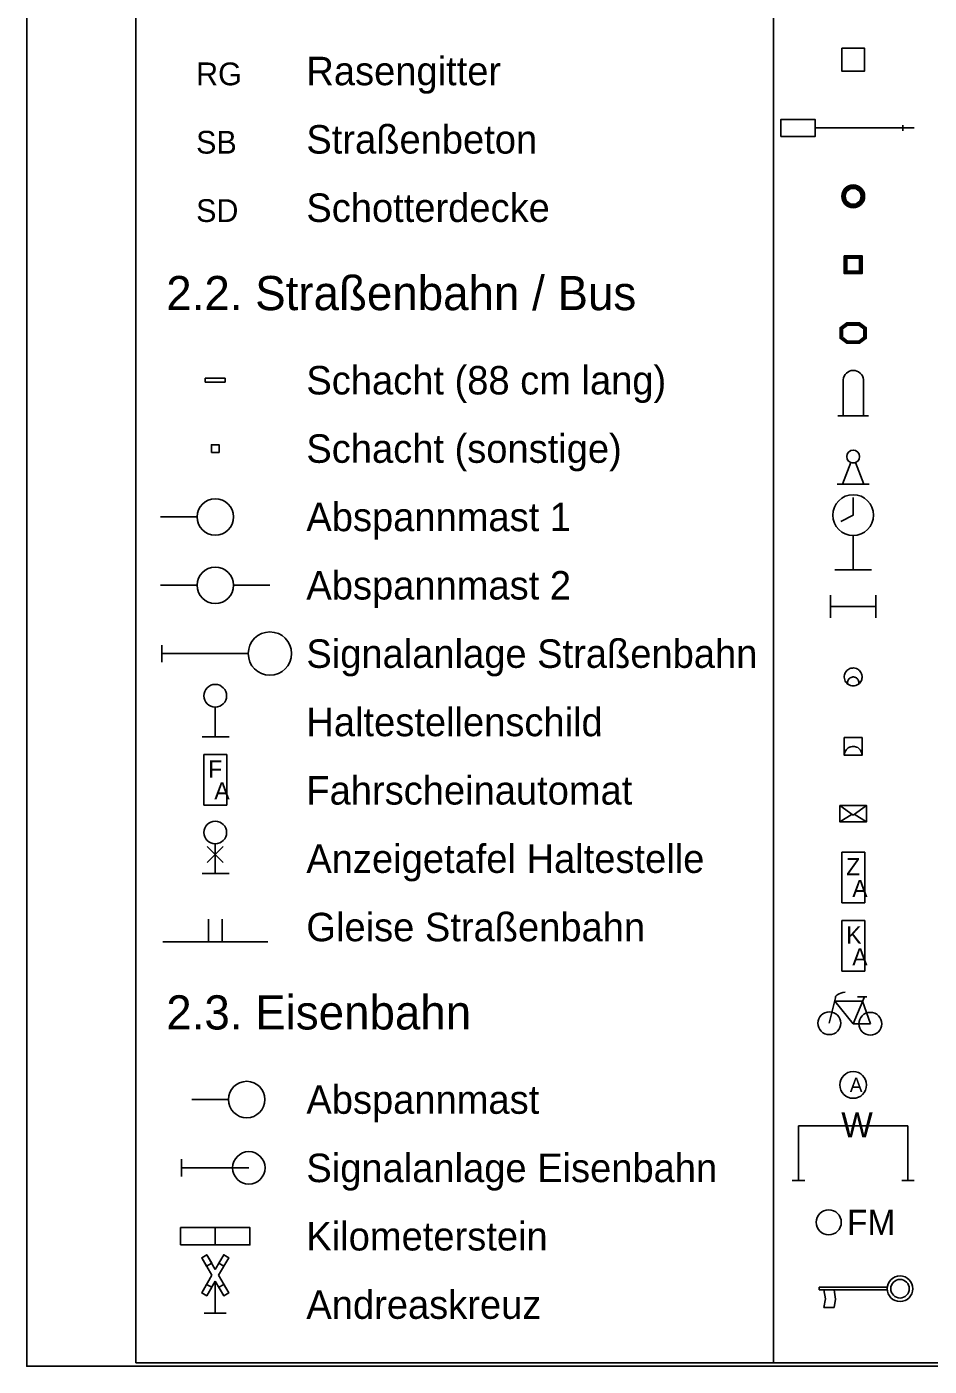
# Model space of a CAD drawing. Extents: x 679244 to 679420, y 5639809 to 5639932.
# Drawn here: x 679243.5 to 679283.1, y 5639808.5 to 5639867.3 of the extents above; entities that cross this region are included whole.
import ezdxf

# ---------------------------------------------------------------- set-up
doc = ezdxf.new("R2010")
doc.units = 0
for name, color, linetype in [('Andreaskreuz', 7, 'Continuous'), ('Anschlagsaeule', 7, 'Continuous'), ('Bank_symbol', 7, 'Continuous'), ('Brandmelder', 7, 'Continuous'), ('Briefkasten', 7, 'Continuous'), ('Deckschicht_text', 7, 'Continuous'), ('Default', 7, 'Continuous'), ('Denkmal', 7, 'Continuous'), ('Eisba_kmstein', 7, 'Continuous'), ('Eisba_mast', 7, 'Continuous'), ('Eisba_signal', 7, 'Continuous'), ('Fahrradstaender_symbol', 7, 'Continuous'), ('Fahrscheinautomat', 7, 'Continuous'), ('Feuermelder', 7, 'Continuous'), ('Haltestelle', 7, 'Continuous'), ('Haltestelle_Anzeige', 7, 'Continuous'), ('Kaugummi', 7, 'Continuous'), ('Kunst_linie', 7, 'Continuous'), ('Mast_stahlgitter', 7, 'Continuous'), ('Papier_eckig', 7, 'Continuous'), ('Papier_rund', 7, 'Continuous'), ('Poller_eckig', 7, 'Continuous'), ('Poller_rund', 7, 'Continuous'), ('Rahmen_1', 7, 'Continuous'), ('Schranke_symbol', 7, 'Continuous'), ('Straba_gleise', 7, 'Continuous'), ('Straba_mast', 7, 'Continuous'), ('Straba_schacht_88', 7, 'Continuous'), ('Straba_schacht_sonst', 7, 'Continuous'), ('Straba_signal', 7, 'Continuous'), ('Uhr', 7, 'Continuous'), ('Werbetafel_symbol', 7, 'Continuous'), ('Zigaretten', 7, 'Continuous')]:
    doc.layers.add(name, color=color, linetype=linetype)

msp = doc.modelspace()

# ---------------------------------------------------------------- linework, layer by layer
at = {"layer": 'Andreaskreuz'}
for p, q in [((679251.778, 5639810.838), (679251.778, 5639812.249)), ((679251.296, 5639810.838), (679252.261, 5639810.838))]:
    msp.add_line(p, q, dxfattribs=at)
for points in [[(679251.407, 5639813.407), (679251.184, 5639813.278), (679251.399, 5639812.906), (679251.622, 5639813.035)], [(679252.149, 5639813.407), (679252.372, 5639813.278), (679252.158, 5639812.906), (679251.935, 5639813.035)], [(679251.184, 5639811.735), (679251.407, 5639811.606), (679251.622, 5639811.978), (679251.399, 5639812.106)], [(679252.149, 5639811.606), (679252.372, 5639811.735), (679252.158, 5639812.106), (679251.935, 5639811.978)]]:
    msp.add_lwpolyline(points, close=True, dxfattribs=at)
for points in [[(679251.778, 5639812.764), (679251.407, 5639813.407), (679251.184, 5639813.278), (679251.63, 5639812.506)], [(679251.927, 5639812.506), (679252.372, 5639813.278), (679252.149, 5639813.407), (679251.778, 5639812.764)], [(679251.63, 5639812.506), (679251.184, 5639811.735), (679251.407, 5639811.606), (679251.778, 5639812.249)], [(679251.778, 5639812.249), (679252.149, 5639811.606), (679252.372, 5639811.735), (679251.927, 5639812.506)]]:
    msp.add_lwpolyline(points, dxfattribs=at)
at = {"layer": 'Anschlagsaeule'}
msp.add_circle((679279.778, 5639820.862), 0.588, dxfattribs=at)
at = {"layer": 'Bank_symbol'}
for p, q in [((679278.778, 5639841.862), (679278.778, 5639842.362)), ((679280.778, 5639841.862), (679280.778, 5639842.362)), ((679278.778, 5639841.862), (679280.778, 5639841.862)), ((679278.778, 5639841.862), (679278.778, 5639841.362)), ((679280.778, 5639841.862), (679280.778, 5639841.362))]:
    msp.add_line(p, q, dxfattribs=at)
at = {"layer": 'Brandmelder'}
for p, q in [((679278.282, 5639811.861), (679278.282, 5639811.987)), ((679278.283, 5639811.987), (679281.274, 5639811.987)), ((679278.283, 5639811.862), (679281.274, 5639811.862)), ((679278.484, 5639811.088), (679278.941, 5639811.088))]:
    msp.add_line(p, q, dxfattribs=at)
for points in [[(679278.493, 5639811.862), (679278.559, 5639811.474), (679278.484, 5639811.088)], [(679278.941, 5639811.088), (679279.004, 5639811.463), (679278.948, 5639811.862)]]:
    msp.add_lwpolyline(points, dxfattribs=at)
for radius in [0.562, 0.407]:
    msp.add_circle((679281.835, 5639811.915), radius, dxfattribs=at)
at = {"layer": 'Briefkasten'}
for p in [(679279.192, 5639833.122), (679280.366, 5639833.122)]:
    msp.add_line(p, (679279.778, 5639832.708), dxfattribs=at)
msp.add_lwpolyline([(679279.192, 5639833.122), (679280.366, 5639833.122), (679280.366, 5639832.412), (679279.192, 5639832.412)], close=True, dxfattribs=at)
for points in [[(679279.192, 5639832.412), (679279.732, 5639832.742)], [(679280.366, 5639832.412), (679279.824, 5639832.74)]]:
    msp.add_lwpolyline(points, dxfattribs=at)
at = {"layer": 'Default'}
for points in [[(679248.286, 5639808.666), (679276.286, 5639808.666), (679276.286, 5639928.666), (679248.286, 5639928.666)], [(679276.286, 5639808.666), (679304.286, 5639808.666), (679304.286, 5639928.666), (679276.286, 5639928.666)]]:
    msp.add_lwpolyline(points, close=True, dxfattribs=at)
at = {"layer": 'Denkmal'}
for p, q in [((679279.344, 5639851.822), (679279.344, 5639850.222)), ((679280.23, 5639851.822), (679280.23, 5639850.222)), ((679280.453, 5639850.222), (679279.103, 5639850.222))]:
    msp.add_line(p, q, dxfattribs=at)
msp.add_arc((679279.787, 5639851.776), 0.445, 5.61466, 175.93727, dxfattribs=at)
at = {"layer": 'Eisba_kmstein'}
for p, q in [((679250.257, 5639814.599), (679253.299, 5639814.599)), ((679250.257, 5639814.599), (679250.257, 5639813.838)), ((679253.299, 5639814.599), (679253.299, 5639813.838)), ((679250.257, 5639813.838), (679253.299, 5639813.838))]:
    msp.add_line(p, q, dxfattribs=at)
msp.add_lwpolyline([(679251.778, 5639814.599), (679251.778, 5639813.838), (679253.299, 5639813.838), (679253.299, 5639814.599)], close=True, dxfattribs=at)
at = {"layer": 'Eisba_mast'}
msp.add_line((679252.357, 5639820.218), (679250.757, 5639820.218), dxfattribs=at)
msp.add_circle((679253.158, 5639820.219), 0.8, dxfattribs=at)
at = {"layer": 'Eisba_signal'}
for p, q in [((679250.304, 5639817.595), (679250.304, 5639816.845)), ((679250.304, 5639817.22), (679253.253, 5639817.22))]:
    msp.add_line(p, q, dxfattribs=at)
msp.add_circle((679253.253, 5639817.22), 0.713, dxfattribs=at)
at = {"layer": 'Fahrradstaender_symbol'}
for p, q in [((679278.73, 5639823.569), (679279.005, 5639824.688)), ((679279.781, 5639823.546), (679278.966, 5639824.531)), ((679279.781, 5639823.546), (679280.27, 5639824.721)), ((679279.975, 5639824.721), (679280.381, 5639824.721)), ((679280.191, 5639824.53), (679280.532, 5639823.545)), ((679279.781, 5639823.546), (679280.532, 5639823.546))]:
    msp.add_line(p, q, dxfattribs=at)
msp.add_lwpolyline([(679278.966, 5639824.531), (679280.191, 5639824.531)], dxfattribs=at)
for centre in [(679278.73, 5639823.569), (679280.532, 5639823.545)]:
    msp.add_circle(centre, 0.5, dxfattribs=at)
msp.add_ellipse((679279.723, 5639824.705), major_axis=(0.72, 0), ratio=0.347019, start_param=2.000612, end_param=3.227598, dxfattribs=at)
at = {"layer": 'Fahrscheinautomat'}
for p, q in [((679252.283, 5639835.368), (679251.274, 5639835.368)), ((679251.274, 5639835.368), (679251.274, 5639833.136)), ((679252.283, 5639833.136), (679252.283, 5639835.368)), ((679251.274, 5639833.136), (679252.283, 5639833.136))]:
    msp.add_line(p, q, dxfattribs=at)
at = {"layer": 'Feuermelder'}
msp.add_circle((679278.706, 5639814.83), 0.55, dxfattribs=at)
at = {"layer": 'Haltestelle'}
for p, q in [((679251.778, 5639837.446), (679251.778, 5639836.136)), ((679251.778, 5639836.136), (679251.206, 5639836.136)), ((679251.778, 5639836.136), (679252.39, 5639836.136))]:
    msp.add_line(p, q, dxfattribs=at)
msp.add_circle((679251.778, 5639837.94), 0.5, dxfattribs=at)
at = {"layer": 'Haltestelle_Anzeige'}
for p, q in [((679251.778, 5639831.446), (679251.778, 5639830.136)), ((679251.422, 5639831.331), (679252.132, 5639830.621)), ((679252.132, 5639831.329), (679251.425, 5639830.622)), ((679251.778, 5639830.136), (679251.206, 5639830.136)), ((679251.778, 5639830.136), (679252.39, 5639830.136))]:
    msp.add_line(p, q, dxfattribs=at)
msp.add_circle((679251.778, 5639831.94), 0.5, dxfattribs=at)
at = {"layer": 'Kaugummi'}
for p, q in [((679280.283, 5639828.081), (679279.274, 5639828.081)), ((679279.274, 5639828.081), (679279.274, 5639825.849)), ((679280.283, 5639825.849), (679280.283, 5639828.081)), ((679279.274, 5639825.849), (679280.283, 5639825.849))]:
    msp.add_line(p, q, dxfattribs=at)
at = {"layer": 'Kunst_linie'}
msp.add_line((679279.074, 5639847.222), (679280.482, 5639847.222), dxfattribs=at)
msp.add_lwpolyline([(679279.677, 5639848.181), (679279.309, 5639847.222), (679280.247, 5639847.222), (679279.878, 5639848.181)], dxfattribs=at)
msp.add_circle((679279.778, 5639848.442), 0.28, dxfattribs=at)
msp.add_arc((679279.778, 5639848.442), 0.28, 248.96249, 291.03746, dxfattribs=at)
at = {"layer": 'Mast_stahlgitter'}
msp.add_lwpolyline([(679279.278, 5639866.362), (679280.278, 5639866.362), (679280.278, 5639865.362), (679279.278, 5639865.362)], close=True, dxfattribs=at)
at = {"layer": 'Papier_eckig'}
for points in [[(679279.388, 5639836.108), (679280.168, 5639836.108), (679280.168, 5639835.328), (679279.388, 5639835.328)], [(679279.388, 5639835.328), (679279.393, 5639835.389), (679279.411, 5639835.455), (679279.426, 5639835.496), (679279.454, 5639835.545), (679279.482, 5639835.581), (679279.523, 5639835.621), (679279.563, 5639835.652), (679279.615, 5639835.68), (679279.633, 5639835.689), (679279.681, 5639835.704), (679279.737, 5639835.715), (679279.778, 5639835.717), (679279.837, 5639835.713), (679279.88, 5639835.704), (679279.927, 5639835.689), (679279.976, 5639835.665), (679280.01, 5639835.642), (679280.042, 5639835.616), (679280.073, 5639835.58), (679280.101, 5639835.548), (679280.12, 5639835.51), (679280.142, 5639835.467), (679280.154, 5639835.427), (679280.165, 5639835.386), (679280.168, 5639835.328), (679280.168, 5639836.108), (679279.388, 5639836.108)]]:
    msp.add_lwpolyline(points, close=True, dxfattribs=at)
at = {"layer": 'Papier_rund'}
msp.add_lwpolyline([(679279.542, 5639838.452), (679279.533, 5639838.493), (679279.532, 5639838.521), (679279.533, 5639838.551), (679279.546, 5639838.598), (679279.558, 5639838.631), (679279.568, 5639838.656), (679279.589, 5639838.682), (679279.612, 5639838.703), (679279.644, 5639838.731), (679279.684, 5639838.75), (679279.729, 5639838.763), (679279.761, 5639838.766), (679279.787, 5639838.766), (679279.829, 5639838.763), (679279.855, 5639838.756), (679279.883, 5639838.745), (679279.917, 5639838.726), (679279.946, 5639838.703), (679279.969, 5639838.675), (679279.99, 5639838.644), (679280.018, 5639838.595), (679280.023, 5639838.558), (679280.023, 5639838.532), (679280.025, 5639838.507), (679280.02, 5639838.477), (679280.013, 5639838.451), (679280.055, 5639838.486), (679280.085, 5639838.521), (679280.12, 5639838.57), (679280.153, 5639838.638), (679280.165, 5639838.693), (679280.169, 5639838.745), (679280.172, 5639838.787), (679280.162, 5639838.854), (679280.146, 5639838.91), (679280.116, 5639838.969), (679280.088, 5639839.009), (679280.058, 5639839.046), (679280.015, 5639839.081), (679279.985, 5639839.102), (679279.929, 5639839.132), (679279.855, 5639839.155), (679279.798, 5639839.162), (679279.743, 5639839.16), (679279.68, 5639839.149), (679279.638, 5639839.135), (679279.581, 5639839.109), (679279.537, 5639839.078), (679279.495, 5639839.044), (679279.463, 5639839.004), (679279.43, 5639838.955), (679279.409, 5639838.91), (679279.397, 5639838.864), (679279.386, 5639838.806), (679279.383, 5639838.756), (679279.39, 5639838.703), (679279.407, 5639838.637), (679279.432, 5639838.579), (679279.462, 5639838.532), (679279.493, 5639838.493), (679279.519, 5639838.472)], close=True, dxfattribs=at)
msp.add_arc((679279.779, 5639838.767), 0.394, 233.0418, 306.52815, dxfattribs=at)
at = {"layer": 'Poller_eckig'}
for points in [[(679279.389, 5639857.251), (679279.389, 5639856.473), (679280.167, 5639856.473), (679280.167, 5639857.251)], [(679279.424, 5639857.216), (679279.424, 5639856.509), (679280.131, 5639856.509), (679280.131, 5639857.216)], [(679279.459, 5639857.18), (679279.459, 5639856.544), (679280.096, 5639856.544), (679280.096, 5639857.18)], [(679279.495, 5639857.145), (679279.495, 5639856.579), (679280.06, 5639856.579), (679280.06, 5639857.145)], [(679279.499, 5639853.412), (679280.056, 5639853.412), (679280.351, 5639853.634), (679280.351, 5639854.091), (679280.057, 5639854.312), (679279.5, 5639854.312), (679279.206, 5639854.091), (679279.206, 5639853.634)], [(679279.516, 5639853.462), (679280.04, 5639853.462), (679280.301, 5639853.659), (679280.301, 5639854.066), (679280.04, 5639854.262), (679279.517, 5639854.262), (679279.256, 5639854.066), (679279.256, 5639853.658)], [(679279.533, 5639853.512), (679280.023, 5639853.512), (679280.251, 5639853.683), (679280.251, 5639854.041), (679280.023, 5639854.212), (679279.533, 5639854.212), (679279.306, 5639854.041), (679279.306, 5639853.683)]]:
    msp.add_lwpolyline(points, close=True, dxfattribs=at)
at = {"layer": 'Poller_rund'}
for radius in [0.5, 0.45, 0.4, 0.35]:
    msp.add_circle((679279.778, 5639859.862), radius, dxfattribs=at)
at = {"layer": 'Rahmen_1'}
msp.add_lwpolyline([(679419.991, 5639808.515), (679243.507, 5639808.515), (679243.507, 5639931.667), (679419.991, 5639931.667)], close=True, dxfattribs=at)
at = {"layer": 'Schranke_symbol'}
for p, q in [((679278.108, 5639862.862), (679282.448, 5639862.862)), ((679281.954, 5639862.862), (679281.954, 5639862.981)), ((679281.954, 5639862.743), (679281.954, 5639862.862))]:
    msp.add_line(p, q, dxfattribs=at)
msp.add_lwpolyline([(679276.608, 5639862.487), (679278.108, 5639862.487), (679278.108, 5639863.237), (679276.608, 5639863.237)], close=True, dxfattribs=at)
at = {"layer": 'Straba_gleise'}
msp.add_line((679249.484, 5639827.136), (679254.084, 5639827.136), dxfattribs=at)
for points in [[(679251.484, 5639827.136), (679251.484, 5639828.136)], [(679252.084, 5639827.136), (679252.084, 5639828.136)]]:
    msp.add_lwpolyline(points, dxfattribs=at)
at = {"layer": 'Straba_mast'}
for p, q in [((679250.978, 5639845.79), (679249.378, 5639845.79)), ((679250.979, 5639842.79), (679249.378, 5639842.79)), ((679254.178, 5639842.792), (679252.579, 5639842.792))]:
    msp.add_line(p, q, dxfattribs=at)
for centre in [(679251.778, 5639845.791), (679251.778, 5639842.791)]:
    msp.add_circle(centre, 0.8, dxfattribs=at)
at = {"layer": 'Straba_schacht_88'}
for p, q in [((679251.338, 5639851.876), (679252.218, 5639851.876)), ((679251.338, 5639851.706), (679251.338, 5639851.876)), ((679252.218, 5639851.706), (679251.338, 5639851.706)), ((679252.218, 5639851.876), (679252.218, 5639851.706))]:
    msp.add_line(p, q, dxfattribs=at)
at = {"layer": 'Straba_schacht_sonst'}
msp.add_lwpolyline([(679251.608, 5639848.621), (679251.948, 5639848.621), (679251.948, 5639848.961), (679251.608, 5639848.961)], close=True, dxfattribs=at)
at = {"layer": 'Straba_signal'}
for p, q in [((679249.428, 5639840.167), (679249.428, 5639839.417)), ((679249.428, 5639839.792), (679253.228, 5639839.792))]:
    msp.add_line(p, q, dxfattribs=at)
msp.add_circle((679254.178, 5639839.792), 0.95, dxfattribs=at)
at = {"layer": 'Uhr'}
msp.add_line((679279.778, 5639845.87), (679279.778, 5639845.87), dxfattribs=at)
for points in [[(679279.778, 5639846.638), (679279.778, 5639845.87), (679279.231, 5639845.597)], [(679279.778, 5639844.974), (679279.778, 5639843.47)], [(679278.978, 5639843.47), (679280.578, 5639843.47)]]:
    msp.add_lwpolyline(points, dxfattribs=at)
msp.add_circle((679279.778, 5639845.87), 0.896, dxfattribs=at)
at = {"layer": 'Werbetafel_symbol'}
for p, q in [((679277.378, 5639819.062), (679282.178, 5639819.062)), ((679277.378, 5639819.062), (679277.378, 5639816.662)), ((679282.178, 5639819.062), (679282.178, 5639816.662)), ((679277.107, 5639816.662), (679277.378, 5639816.662)), ((679277.378, 5639816.662), (679277.649, 5639816.662)), ((679281.907, 5639816.662), (679282.178, 5639816.662)), ((679282.178, 5639816.662), (679282.449, 5639816.662))]:
    msp.add_line(p, q, dxfattribs=at)
at = {"layer": 'Zigaretten'}
for p, q in [((679280.283, 5639831.081), (679279.274, 5639831.081)), ((679279.274, 5639831.081), (679279.274, 5639828.849)), ((679280.283, 5639828.849), (679280.283, 5639831.081)), ((679279.274, 5639828.849), (679280.283, 5639828.849))]:
    msp.add_line(p, q, dxfattribs=at)

# ---------------------------------------------------------------- texts
at = {"layer": 'Anschlagsaeule'}
msp.add_text('A', height=0.625, dxfattribs=at).set_placement((679279.629, 5639820.55))
at = {"layer": 'Deckschicht_text'}
for s, p in [('RG', (679250.938, 5639864.736)), ('SB', (679250.938, 5639861.736)), ('SD', (679250.938, 5639858.736))]:
    msp.add_text(s, height=1, dxfattribs=at).set_placement(p)
at = {"layer": 'Default'}
for s, height, p in [('Rasengitter', 1.25, (679255.778, 5639864.738)), ('Straßenbeton', 1.25, (679255.778, 5639861.738)), ('Schotterdecke', 1.25, (679255.778, 5639858.738)), ('2.2. Straßenbahn / Bus', 1.5, (679249.628, 5639854.866)), ('Schacht (88 cm lang)', 1.25, (679255.778, 5639851.166)), ('Schacht (sonstige)', 1.25, (679255.778, 5639848.166)), ('Abspannmast 1', 1.25, (679255.778, 5639845.166)), ('Abspannmast 2', 1.25, (679255.778, 5639842.166)), ('Signalanlage Straßenbahn', 1.25, (679255.778, 5639839.166)), ('Haltestellenschild', 1.25, (679255.778, 5639836.166)), ('Fahrscheinautomat', 1.25, (679255.778, 5639833.166)), ('Anzeigetafel Haltestelle', 1.25, (679255.778, 5639830.166)), ('Gleise Straßenbahn', 1.25, (679255.778, 5639827.166)), ('2.3. Eisenbahn', 1.5, (679249.628, 5639823.294)), ('Abspannmast', 1.25, (679255.778, 5639819.594)), ('Signalanlage Eisenbahn', 1.25, (679255.778, 5639816.594)), ('Kilometerstein', 1.25, (679255.778, 5639813.594)), ('Andreaskreuz', 1.25, (679255.778, 5639810.594))]:
    msp.add_text(s, height=height, dxfattribs=at).set_placement(p)
at = {"layer": 'Fahrscheinautomat'}
for s, p in [('F', (679251.473, 5639834.353)), ('A', (679251.74, 5639833.399))]:
    msp.add_text(s, height=0.75, dxfattribs=at).set_placement(p)
at = {"layer": 'Feuermelder'}
msp.add_text('FM', height=1.099, dxfattribs=at).set_placement((679279.506, 5639814.28))
at = {"layer": 'Kaugummi'}
for s, p in [('K', (679279.473, 5639827.065)), ('A', (679279.74, 5639826.111))]:
    msp.add_text(s, height=0.75, dxfattribs=at).set_placement(p)
at = {"layer": 'Werbetafel_symbol'}
msp.add_text('W', height=1.099, dxfattribs=at).set_placement((679279.254, 5639818.562))
at = {"layer": 'Zigaretten'}
for s, p in [('Z', (679279.473, 5639830.066)), ('A', (679279.74, 5639829.112))]:
    msp.add_text(s, height=0.75, dxfattribs=at).set_placement(p)

doc.saveas('drawing.dxf')
